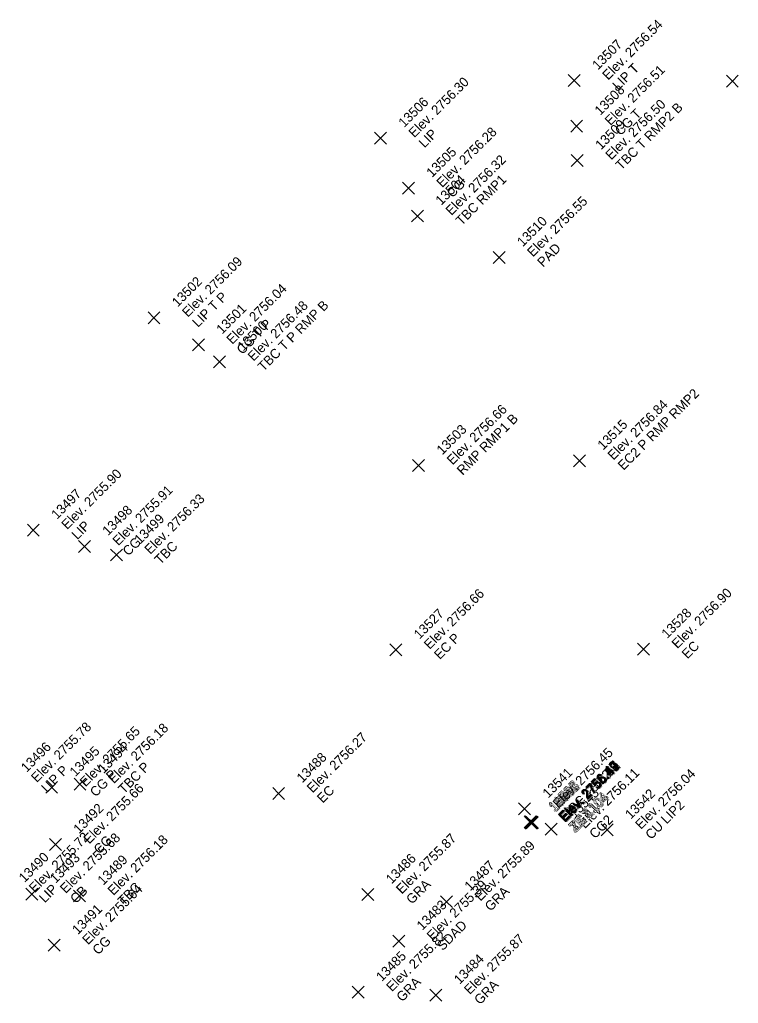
# Model space of a CAD drawing. Extents: x 2493999 to 2503109, y 700767 to 706646.
# Drawn here: x 2502319.88 to 2502337.9, y 703160.33 to 703185 of the extents above; entities that cross this region are included whole.
import ezdxf

# ---------------------------------------------------------------- set-up
doc = ezdxf.new("R2010")
doc.units = 0
doc.layers.add('ALG_CL_BLUE_Horiz', color=7, linetype='Continuous')
doc.layers.add('DES_SURFACE_Existing-Ground', color=7, linetype='Continuous')

msp = doc.modelspace()

# ---------------------------------------------------------------- linework, layer by layer
at = {"layer": 'ALG_CL_BLUE_Horiz'}
for points in [[(2502333.787, 703183.472), (2502333.637, 703183.622), (2502333.787, 703183.472), (2502333.637, 703183.322), (2502333.787, 703183.472), (2502333.937, 703183.322), (2502333.787, 703183.472), (2502333.937, 703183.622)], [(2502337.751, 703183.457), (2502337.601, 703183.607), (2502337.751, 703183.457), (2502337.601, 703183.307), (2502337.751, 703183.457), (2502337.901, 703183.307), (2502337.751, 703183.457), (2502337.901, 703183.607)], [(2502333.847, 703182.332), (2502333.697, 703182.482), (2502333.847, 703182.332), (2502333.697, 703182.182), (2502333.847, 703182.332), (2502333.997, 703182.182), (2502333.847, 703182.332), (2502333.997, 703182.482)], [(2502328.928, 703182.027), (2502328.778, 703182.177), (2502328.928, 703182.027), (2502328.778, 703181.877), (2502328.928, 703182.027), (2502329.078, 703181.877), (2502328.928, 703182.027), (2502329.078, 703182.177)], [(2502333.863, 703181.468), (2502333.713, 703181.618), (2502333.863, 703181.468), (2502333.713, 703181.318), (2502333.863, 703181.468), (2502334.013, 703181.318), (2502333.863, 703181.468), (2502334.013, 703181.618)], [(2502329.628, 703180.774), (2502329.478, 703180.924), (2502329.628, 703180.774), (2502329.478, 703180.624), (2502329.628, 703180.774), (2502329.778, 703180.624), (2502329.628, 703180.774), (2502329.778, 703180.924)], [(2502329.856, 703180.076), (2502329.706, 703180.226), (2502329.856, 703180.076), (2502329.706, 703179.926), (2502329.856, 703180.076), (2502330.006, 703179.926), (2502329.856, 703180.076), (2502330.006, 703180.226)], [(2502331.902, 703179.036), (2502331.752, 703179.186), (2502331.902, 703179.036), (2502331.752, 703178.886), (2502331.902, 703179.036), (2502332.052, 703178.886), (2502331.902, 703179.036), (2502332.052, 703179.186)], [(2502323.248, 703177.524), (2502323.098, 703177.674), (2502323.248, 703177.524), (2502323.098, 703177.374), (2502323.248, 703177.524), (2502323.398, 703177.374), (2502323.248, 703177.524), (2502323.398, 703177.674)], [(2502324.361, 703176.842), (2502324.211, 703176.992), (2502324.361, 703176.842), (2502324.211, 703176.692), (2502324.361, 703176.842), (2502324.511, 703176.692), (2502324.361, 703176.842), (2502324.511, 703176.992)], [(2502324.892, 703176.418), (2502324.742, 703176.568), (2502324.892, 703176.418), (2502324.742, 703176.268), (2502324.892, 703176.418), (2502325.042, 703176.268), (2502324.892, 703176.418), (2502325.042, 703176.568)], [(2502329.884, 703173.815), (2502329.734, 703173.965), (2502329.884, 703173.815), (2502329.734, 703173.665), (2502329.884, 703173.815), (2502330.034, 703173.665), (2502329.884, 703173.815), (2502330.034, 703173.965)], [(2502333.918, 703173.937), (2502333.768, 703174.087), (2502333.918, 703173.937), (2502333.768, 703173.787), (2502333.918, 703173.937), (2502334.068, 703173.787), (2502333.918, 703173.937), (2502334.068, 703174.087)], [(2502320.222, 703172.198), (2502320.072, 703172.348), (2502320.222, 703172.198), (2502320.072, 703172.048), (2502320.222, 703172.198), (2502320.372, 703172.048), (2502320.222, 703172.198), (2502320.372, 703172.348)], [(2502321.502, 703171.789), (2502321.352, 703171.939), (2502321.502, 703171.789), (2502321.352, 703171.639), (2502321.502, 703171.789), (2502321.652, 703171.639), (2502321.502, 703171.789), (2502321.652, 703171.939)], [(2502322.304, 703171.573), (2502322.154, 703171.723), (2502322.304, 703171.573), (2502322.154, 703171.423), (2502322.304, 703171.573), (2502322.454, 703171.423), (2502322.304, 703171.573), (2502322.454, 703171.723)], [(2502329.313, 703169.192), (2502329.163, 703169.342), (2502329.313, 703169.192), (2502329.163, 703169.042), (2502329.313, 703169.192), (2502329.463, 703169.042), (2502329.313, 703169.192), (2502329.463, 703169.342)], [(2502335.524, 703169.209), (2502335.374, 703169.359), (2502335.524, 703169.209), (2502335.374, 703169.059), (2502335.524, 703169.209), (2502335.674, 703169.059), (2502335.524, 703169.209), (2502335.674, 703169.359)], [(2502320.682, 703165.744), (2502320.532, 703165.894), (2502320.682, 703165.744), (2502320.532, 703165.594), (2502320.682, 703165.744), (2502320.832, 703165.594), (2502320.682, 703165.744), (2502320.832, 703165.894)], [(2502321.392, 703165.821), (2502321.242, 703165.971), (2502321.392, 703165.821), (2502321.242, 703165.671), (2502321.392, 703165.821), (2502321.542, 703165.671), (2502321.392, 703165.821), (2502321.542, 703165.971)], [(2502326.374, 703165.588), (2502326.224, 703165.738), (2502326.374, 703165.588), (2502326.224, 703165.438), (2502326.374, 703165.588), (2502326.524, 703165.438), (2502326.374, 703165.588), (2502326.524, 703165.738)], [(2502332.541, 703165.204), (2502332.391, 703165.354), (2502332.541, 703165.204), (2502332.391, 703165.054), (2502332.541, 703165.204), (2502332.691, 703165.054), (2502332.541, 703165.204), (2502332.691, 703165.354)], [(2502332.678, 703164.879), (2502332.528, 703165.029), (2502332.678, 703164.879), (2502332.528, 703164.729), (2502332.678, 703164.879), (2502332.828, 703164.729), (2502332.678, 703164.879), (2502332.828, 703165.029)], [(2502332.687, 703164.873), (2502332.537, 703165.023), (2502332.687, 703164.873), (2502332.537, 703164.723), (2502332.687, 703164.873), (2502332.837, 703164.723), (2502332.687, 703164.873), (2502332.837, 703165.023)], [(2502332.691, 703164.873), (2502332.541, 703165.023), (2502332.691, 703164.873), (2502332.541, 703164.723), (2502332.691, 703164.873), (2502332.841, 703164.723), (2502332.691, 703164.873), (2502332.841, 703165.023)], [(2502332.696, 703164.854), (2502332.546, 703165.004), (2502332.696, 703164.854), (2502332.546, 703164.704), (2502332.696, 703164.854), (2502332.846, 703164.704), (2502332.696, 703164.854), (2502332.846, 703165.004)], [(2502332.701, 703164.876), (2502332.551, 703165.026), (2502332.701, 703164.876), (2502332.551, 703164.726), (2502332.701, 703164.876), (2502332.851, 703164.726), (2502332.701, 703164.876), (2502332.851, 703165.026)], [(2502332.704, 703164.868), (2502332.554, 703165.018), (2502332.704, 703164.868), (2502332.554, 703164.718), (2502332.704, 703164.868), (2502332.854, 703164.718), (2502332.704, 703164.868), (2502332.854, 703165.018)], [(2502332.709, 703164.867), (2502332.559, 703165.017), (2502332.709, 703164.867), (2502332.559, 703164.717), (2502332.709, 703164.867), (2502332.859, 703164.717), (2502332.709, 703164.867), (2502332.859, 703165.017)], [(2502332.709, 703164.855), (2502332.559, 703165.005), (2502332.709, 703164.855), (2502332.559, 703164.705), (2502332.709, 703164.855), (2502332.859, 703164.705), (2502332.709, 703164.855), (2502332.859, 703165.005)], [(2502332.711, 703164.868), (2502332.561, 703165.018), (2502332.711, 703164.868), (2502332.561, 703164.718), (2502332.711, 703164.868), (2502332.861, 703164.718), (2502332.711, 703164.868), (2502332.861, 703165.018)], [(2502332.715, 703164.87), (2502332.565, 703165.02), (2502332.715, 703164.87), (2502332.565, 703164.72), (2502332.715, 703164.87), (2502332.865, 703164.72), (2502332.715, 703164.87), (2502332.865, 703165.02)], [(2502332.718, 703164.857), (2502332.568, 703165.007), (2502332.718, 703164.857), (2502332.568, 703164.707), (2502332.718, 703164.857), (2502332.868, 703164.707), (2502332.718, 703164.857), (2502332.868, 703165.007)], [(2502332.727, 703164.865), (2502332.577, 703165.015), (2502332.727, 703164.865), (2502332.577, 703164.715), (2502332.727, 703164.865), (2502332.877, 703164.715), (2502332.727, 703164.865), (2502332.877, 703165.015)], [(2502332.728, 703164.861), (2502332.578, 703165.011), (2502332.728, 703164.861), (2502332.578, 703164.711), (2502332.728, 703164.861), (2502332.878, 703164.711), (2502332.728, 703164.861), (2502332.878, 703165.011)], [(2502332.73, 703164.867), (2502332.58, 703165.017), (2502332.73, 703164.867), (2502332.58, 703164.717), (2502332.73, 703164.867), (2502332.88, 703164.717), (2502332.73, 703164.867), (2502332.88, 703165.017)], [(2502332.731, 703164.854), (2502332.581, 703165.004), (2502332.731, 703164.854), (2502332.581, 703164.704), (2502332.731, 703164.854), (2502332.881, 703164.704), (2502332.731, 703164.854), (2502332.881, 703165.004)], [(2502332.735, 703164.866), (2502332.585, 703165.016), (2502332.735, 703164.866), (2502332.585, 703164.716), (2502332.735, 703164.866), (2502332.885, 703164.716), (2502332.735, 703164.866), (2502332.885, 703165.016)], [(2502333.206, 703164.696), (2502333.056, 703164.846), (2502333.206, 703164.696), (2502333.056, 703164.546), (2502333.206, 703164.696), (2502333.356, 703164.546), (2502333.206, 703164.696), (2502333.356, 703164.846)], [(2502334.611, 703164.675), (2502334.461, 703164.825), (2502334.611, 703164.675), (2502334.461, 703164.525), (2502334.611, 703164.675), (2502334.761, 703164.525), (2502334.611, 703164.675), (2502334.761, 703164.825)], [(2502320.776, 703164.31), (2502320.626, 703164.46), (2502320.776, 703164.31), (2502320.626, 703164.16), (2502320.776, 703164.31), (2502320.926, 703164.16), (2502320.776, 703164.31), (2502320.926, 703164.46)], [(2502320.187, 703163.068), (2502320.037, 703163.218), (2502320.187, 703163.068), (2502320.037, 703162.918), (2502320.187, 703163.068), (2502320.337, 703162.918), (2502320.187, 703163.068), (2502320.337, 703163.218)], [(2502321.382, 703163.019), (2502321.232, 703163.169), (2502321.382, 703163.019), (2502321.232, 703162.869), (2502321.382, 703163.019), (2502321.532, 703162.869), (2502321.382, 703163.019), (2502321.532, 703163.169)], [(2502328.613, 703163.053), (2502328.463, 703163.203), (2502328.613, 703163.053), (2502328.463, 703162.903), (2502328.613, 703163.053), (2502328.763, 703162.903), (2502328.613, 703163.053), (2502328.763, 703163.203)], [(2502330.584, 703162.876), (2502330.434, 703163.026), (2502330.584, 703162.876), (2502330.434, 703162.726), (2502330.584, 703162.876), (2502330.734, 703162.726), (2502330.584, 703162.876), (2502330.734, 703163.026)], [(2502320.745, 703161.782), (2502320.595, 703161.932), (2502320.745, 703161.782), (2502320.595, 703161.632), (2502320.745, 703161.782), (2502320.895, 703161.632), (2502320.745, 703161.782), (2502320.895, 703161.932)], [(2502329.384, 703161.887), (2502329.234, 703162.037), (2502329.384, 703161.887), (2502329.234, 703161.737), (2502329.384, 703161.887), (2502329.534, 703161.737), (2502329.384, 703161.887), (2502329.534, 703162.037)], [(2502328.368, 703160.604), (2502328.218, 703160.754), (2502328.368, 703160.604), (2502328.218, 703160.454), (2502328.368, 703160.604), (2502328.518, 703160.454), (2502328.368, 703160.604), (2502328.518, 703160.754)], [(2502330.319, 703160.532), (2502330.169, 703160.682), (2502330.319, 703160.532), (2502330.169, 703160.382), (2502330.319, 703160.532), (2502330.469, 703160.382), (2502330.319, 703160.532), (2502330.469, 703160.682)]]:
    msp.add_lwpolyline(points, dxfattribs=at)

# ---------------------------------------------------------------- texts
at = {"layer": 'DES_SURFACE_Existing-Ground'}
for s, p in [('Elev. 2756.54', (2502334.636, 703183.472)), ('13507', (2502334.381, 703183.727)), ('Elev. 2756.51', (2502334.696, 703182.332)), ('LIP T', (2502334.89, 703183.217)), ('Elev. 2756.30', (2502329.777, 703182.027)), ('13508', (2502334.441, 703182.587)), ('13506', (2502329.522, 703182.282)), ('Elev. 2756.50', (2502334.712, 703181.468)), ('TBC T RMP2 B', (2502334.966, 703181.213)), ('CG T', (2502334.95, 703182.077)), ('13509', (2502334.457, 703181.723)), ('LIP', (2502330.031, 703181.772)), ('Elev. 2756.28', (2502330.477, 703180.774)), ('13505', (2502330.222, 703181.029)), ('Elev. 2756.32', (2502330.705, 703180.076)), ('13504', (2502330.45, 703180.331)), ('CG', (2502330.731, 703180.519)), ('TBC RMP1', (2502330.959, 703179.821)), ('Elev. 2756.55', (2502332.751, 703179.036)), ('13510', (2502332.496, 703179.291)), ('PAD', (2502333.005, 703178.781)), ('Elev. 2756.09', (2502324.097, 703177.524)), ('13502', (2502323.842, 703177.779)), ('LIP T P', (2502324.351, 703177.269)), ('Elev. 2756.04', (2502325.21, 703176.842)), ('Elev. 2756.48', (2502325.741, 703176.418)), ('TBC T P RMP B', (2502325.995, 703176.163)), ('13501', (2502324.955, 703177.097)), ('CG T P', (2502325.464, 703176.587)), ('13500', (2502325.486, 703176.673)), ('EC2 P RMP RMP2', (2502335.021, 703173.682)), ('Elev. 2756.84', (2502334.767, 703173.937)), ('Elev. 2756.66', (2502330.733, 703173.815)), ('RMP RMP1 B', (2502330.987, 703173.56)), ('13515', (2502334.512, 703174.192)), ('13503', (2502330.478, 703174.07)), ('Elev. 2755.90', (2502321.071, 703172.198)), ('13497', (2502320.816, 703172.453)), ('Elev. 2755.91', (2502322.351, 703171.789)), ('Elev. 2756.33', (2502323.153, 703171.573)), ('13498', (2502322.096, 703172.044)), ('13499', (2502322.898, 703171.828)), ('LIP', (2502321.325, 703171.943)), ('CG', (2502322.605, 703171.534)), ('TBC', (2502323.407, 703171.318)), ('Elev. 2756.66', (2502330.162, 703169.192)), ('Elev. 2756.90', (2502336.373, 703169.209)), ('13527', (2502329.907, 703169.447)), ('13528', (2502336.118, 703169.464)), ('EC P', (2502330.416, 703168.937)), ('EC', (2502336.627, 703168.954)), ('Elev. 2755.78', (2502320.31, 703165.85)), ('Elev. 2756.18', (2502322.241, 703165.821)), ('Elev. 2755.65', (2502321.531, 703165.744)), ('Elev. 2756.27', (2502327.223, 703165.588)), ('13496', (2502320.055, 703166.105)), ('13494', (2502321.986, 703166.076)), ('13495', (2502321.276, 703165.999)), ('13488', (2502326.968, 703165.843)), ('Elev. 2756.45', (2502333.39, 703165.204)), ('TBC P', (2502322.495, 703165.566)), ('Elev. 2756.49', (2502333.527, 703164.879)), ('Elev. 2756.49', (2502333.536, 703164.873)), ('Elev. 2756.47', (2502333.54, 703164.873)), ('Elev. 2756.49', (2502333.545, 703164.854)), ('Elev. 2756.47', (2502333.55, 703164.876)), ('Elev. 2756.52', (2502333.553, 703164.868)), ('Elev. 2756.50', (2502333.558, 703164.867)), ('Elev. 2756.48', (2502333.558, 703164.855)), ('Elev. 2756.51', (2502333.56, 703164.868)), ('Elev. 2756.47', (2502333.564, 703164.87)), ('Elev. 2756.48', (2502333.567, 703164.857)), ('Elev. 2756.50', (2502333.576, 703164.865)), ('Elev. 2756.51', (2502333.577, 703164.861)), ('Elev. 2756.46', (2502333.579, 703164.867)), ('Elev. 2756.47', (2502333.58, 703164.854)), ('Elev. 2756.48', (2502333.584, 703164.866)), ('LIP P', (2502320.564, 703165.595)), ('CG P', (2502321.785, 703165.489)), ('13541', (2502333.135, 703165.459)), ('TBC TBC2', (2502333.644, 703164.949)), ('Elev. 2756.11', (2502334.055, 703164.696)), ('Elev. 2756.04', (2502335.46, 703164.675)), ('Elev. 2755.66', (2502321.625, 703164.31)), ('11735', (2502333.272, 703165.134)), ('13135', (2502333.281, 703165.128)), ('11734', (2502333.285, 703165.128)), ('14161', (2502333.29, 703165.109)), ('12317', (2502333.295, 703165.131)), ('13546', (2502333.298, 703165.123)), ('13136', (2502333.303, 703165.122)), ('12322', (2502333.303, 703165.11)), ('16953', (2502333.305, 703165.123)), ('18357', (2502333.309, 703165.125)), ('15627', (2502333.312, 703165.112)), ('14183', (2502333.321, 703165.12)), ('15626', (2502333.324, 703165.122)), ('10002', (2502333.325, 703165.109)), ('10064', (2502333.329, 703165.121)), ('EC', (2502327.477, 703165.333)), ('1104', (2502333.322, 703165.116)), ('ZK 1104', (2502333.781, 703164.624)), ('ZK 1104', (2502333.79, 703164.618)), ('ZK 1104', (2502333.794, 703164.618)), ('ZK 1104', (2502333.799, 703164.599)), ('ZK 1104', (2502333.804, 703164.621)), ('ZK 1104', (2502333.807, 703164.613)), ('ZK 1104', (2502333.812, 703164.612)), ('ZK 1104', (2502333.812, 703164.6)), ('ZK 1104', (2502333.814, 703164.613)), ('ZK 1104', (2502333.818, 703164.615)), ('ZK 1104', (2502333.821, 703164.602)), ('ZK 1104', (2502333.83, 703164.61)), ('ZK 1104', (2502333.833, 703164.612)), ('13543', (2502333.8, 703164.951)), ('ZK 1104', (2502333.834, 703164.599)), ('ZK 1104', (2502333.838, 703164.611)), ('13542', (2502335.205, 703164.93)), ('13492', (2502321.37, 703164.565)), ('CU LIP2', (2502335.714, 703164.42)), ('XSX', (2502333.831, 703164.606)), ('CG2', (2502334.309, 703164.441)), ('Elev. 2755.72', (2502320.255, 703163.085)), ('Elev. 2755.68', (2502321.036, 703163.068)), ('Elev. 2755.87', (2502329.462, 703163.053)), ('CG', (2502321.879, 703164.055)), ('Elev. 2756.18', (2502322.231, 703163.019)), ('Elev. 2755.89', (2502331.433, 703162.876)), ('13490', (2502320, 703163.34)), ('13493', (2502320.781, 703163.323)), ('13486', (2502329.207, 703163.308)), ('13489', (2502321.976, 703163.274)), ('13487', (2502331.178, 703163.131)), ('TBC', (2502322.485, 703162.764)), ('GRA', (2502329.716, 703162.798)), ('Elev. 2755.39', (2502330.233, 703161.887)), ('LIP', (2502320.509, 703162.83)), ('CB', (2502321.29, 703162.813)), ('Elev. 2755.64', (2502321.594, 703161.782)), ('GRA', (2502331.687, 703162.621)), ('13483', (2502329.978, 703162.142)), ('13491', (2502321.339, 703162.037)), ('SDAD', (2502330.487, 703161.632)), ('Elev. 2755.82', (2502329.217, 703160.604)), ('CG', (2502321.848, 703161.527)), ('Elev. 2755.87', (2502331.168, 703160.532)), ('13485', (2502328.962, 703160.859)), ('13484', (2502330.913, 703160.787)), ('GRA', (2502329.471, 703160.349)), ('GRA', (2502331.422, 703160.277))]:
    msp.add_text(s, height=0.24, rotation=45, dxfattribs=at).set_placement(p)

doc.saveas('drawing.dxf')
